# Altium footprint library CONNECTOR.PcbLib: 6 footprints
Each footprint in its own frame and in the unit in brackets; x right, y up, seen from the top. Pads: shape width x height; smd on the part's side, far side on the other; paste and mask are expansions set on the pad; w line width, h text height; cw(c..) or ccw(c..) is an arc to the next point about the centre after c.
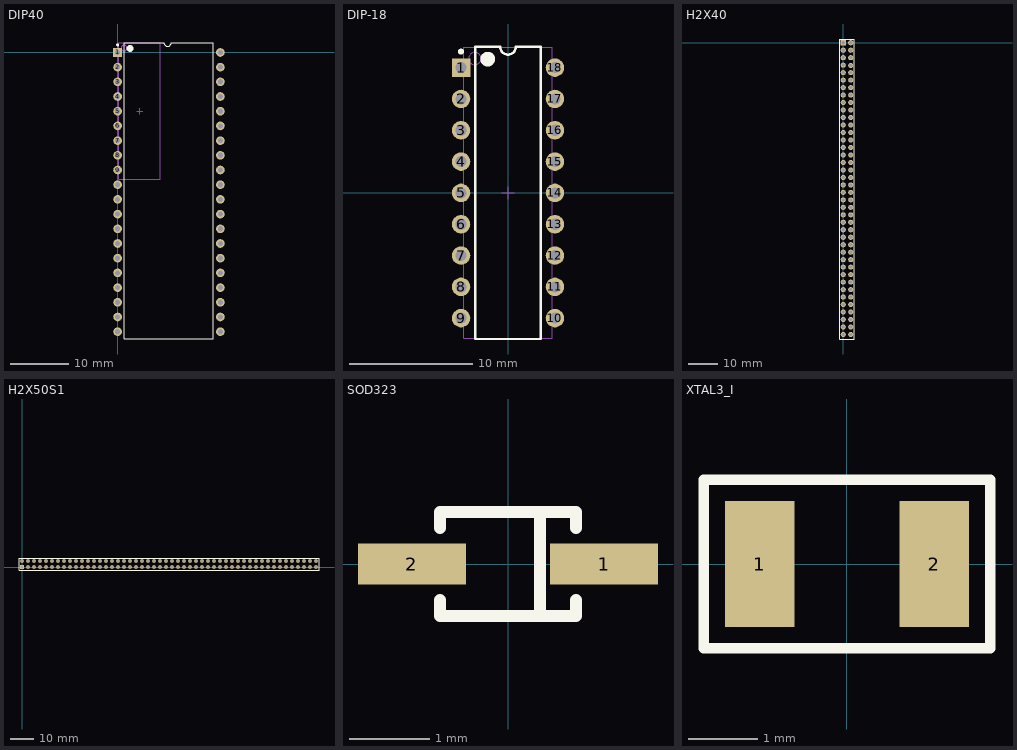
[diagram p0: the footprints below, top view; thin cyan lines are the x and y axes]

## DIP40 [mm] "DIP; 40"
pads (40):
  rect 1.5x1.5 hole 0.9: 1(0,0)
  round 1.5 hole 0.9: 2(0,-2.54) 3(0,-5.08) 4(0,-7.62) 5(0,-10.16) 6(0,-12.7) 7(0,-15.24) 8(0,-17.78) 9(0,-20.32) 10(0,-22.86) 11(0,-25.4) 12(0,-27.94) 13(0,-30.48) 14(0,-33.02) 15(0,-35.56) 16(0,-38.1) 17(0,-40.64) 18(0,-43.18) 19(0,-45.72) 20(0,-48.26) 21(17.78,0) 22(17.78,-2.54) 23(17.78,-5.08) 24(17.78,-7.62) 25(17.78,-10.16) 26(17.78,-12.7) 27(17.78,-15.24) 28(17.78,-17.78) 29(17.78,-20.32) 30(17.78,-22.86) 31(17.78,-25.4) 32(17.78,-27.94) 33(17.78,-30.48) 34(17.78,-33.02) 35(17.78,-35.56) 36(17.78,-38.1) 37(17.78,-40.64) 38(17.78,-43.18) 39(17.78,-45.72) 40(17.78,-48.26)
Top Overlay:
  circle w0.25: c0,1.3 r0.125
  circle w0.6: c2.16,0.69 r0.3
  lines w0.2: 3.175,1.69 1.16,1.69 1.16,-49.53 16.51,-49.53 16.51,1.69
  lines w0.203: 2.54,1.69 8.001,1.69 ccw(c8.636,1.69) 9.271,1.69 16.51,1.69
Mechanical 13:
  circle w0.1: c1.11,0.74 r0.5
  lines w0.1: 0.21,-21.96 0.21,1.64 7.41,1.64 7.41,-21.96 0.21,-21.96
Mechanical 15:
  lines w0.1: 3.31,-10.16 4.31,-10.16 ; 3.81,-10.66 3.81,-9.66

## DIP-18 [mm] "DIP; 18 Leads; Row Spacing 7.62 mm; Pitch 2.54 mm"
height 5.08
pads (18):
  rect 1.5x1.5 hole 0.9: 1(-3.81,10.16)
  round 1.5 hole 0.9: 2(-3.81,7.62) 3(-3.81,5.08) 4(-3.81,2.54) 5(-3.81,0) 6(-3.81,-2.54) 7(-3.81,-5.08) 8(-3.81,-7.62) 9(-3.81,-10.16) 10(3.81,-10.16) 11(3.81,-7.62) 12(3.81,-5.08) 13(3.81,-2.54) 14(3.81,0) 15(3.81,2.54) 16(3.81,5.08) 17(3.81,7.62) 18(3.81,10.16)
Top Overlay:
  circle w0.25: c-3.81,11.46 r0.125
  circle w0.6: c-1.65,10.85 r0.3
  lines w0.2: -2.65,-11.85 -2.65,11.85 -0.635,11.85 ccw(c0,11.85) 0.635,11.85 2.65,11.85 2.65,-11.85 -2.65,-11.85
Mechanical 13:
  circle w0.1: c-2.7,10.9 r0.5
  lines w0.1: -3.6,-11.8 -3.6,11.8 3.6,11.8 3.6,-11.8 -3.6,-11.8
Mechanical 15:
  lines w0.1: -0.5,0 0.5,0 ; 0,-0.5 0,0.5
3D body: height 5.08, standoff 0, extent -3.6,-11.8 3.6,11.8

## H2X40 [mil]
height 330
pads (80):
  rect 68x68 hole 41: 1(0,0)
  round 68 hole 41: 2(100,0) 3(0,-100) 4(100,-100) 5(0,-200) 6(100,-200) 7(0,-300) 8(100,-303) 9(0,-400) 10(100,-400) 11(0,-500) 12(100,-500) 13(0,-600) 14(100,-600) 15(0,-700) 16(100,-700) 17(0,-800) 18(100,-800) 19(0,-900) 20(100,-900) 21(0,-1000) 22(100,-1000) 23(0,-1100) 24(100,-1100) 25(0,-1200) 26(100,-1200) 27(0,-1300) 28(100,-1300) 29(0,-1400) 30(100,-1400) 31(0,-1500) 32(100,-1500) 33(0,-1600) 34(100,-1600) 35(0,-1700) 36(100,-1700) 37(0,-1800) 38(100,-1800) 39(0,-1900) 40(100,-1900) 41(0,-2000) 42(100,-2000) 43(0,-2100) 44(100,-2100) 45(0,-2200) 46(100,-2200) 47(0,-2300) 48(100,-2300) 49(0,-2400) 50(100,-2400) 51(0,-2500) 52(100,-2500) 53(0,-2600) 54(100,-2600) 55(0,-2700) 56(100,-2700) 57(0,-2800) 58(100,-2800) 59(0,-2900) 60(100,-2900) 61(0,-3000) 62(100,-3000) 63(0,-3100) 64(100,-3100) 65(0,-3200) 66(100,-3200) 67(0,-3300) 68(100,-3300) 69(0,-3400) 70(100,-3400) 71(0,-3500) 72(100,-3500) 73(0,-3600) 74(100,-3600) 75(0,-3700) 76(100,-3700) 77(0,-3800) 78(100,-3800) 79(0,-3900) 80(100,-3900)
Top Overlay:
  lines w8: -50,-3960 -50,50 150,50 150,-3960 -50,-3960

## H2X50S1 [mil]
height 330
pads (100):
  rect 62x62 hole 36: 1(0,0)
  round 62 hole 36: 2(0,100) 3(100,0) 4(100,100) 5(200,0) 6(200,100) 7(300,0) 8(300,100) 9(400,0) 10(400,100) 11(500,0) 12(500,100) 13(600,0) 14(600,100) 15(700,0) 16(700,100) 17(800,0) 18(800,100) 19(900,0) 20(900,100) 21(1000,0) 22(1000,100) 23(1100,0) 24(1100,100) 25(1200,0) 26(1200,100) 27(1300,0) 28(1300,100) 29(1400,0) 30(1400,100) 31(1500,0) 32(1500,100) 33(1600,0) 34(1600,100) 35(1700,0) 36(1700,100) 37(1800,0) 38(1800,100) 39(1900,0) 40(1900,100) 41(2000,0) 42(2000,100) 43(2100,0) 44(2100,100) 45(2200,0) 46(2200,100) 47(2300,0) 48(2300,100) 49(2400,0) 50(2400,100) 51(2500,0) 52(2500,100) 53(2600,0) 54(2600,100) 55(2700,0) 56(2700,100) 57(2800,0) 58(2800,100) 59(2900,0) 60(2900,100) 61(3000,0) 62(3000,100) 63(3100,0) 64(3100,100) 65(3200,0) 66(3200,100) 67(3300,0) 68(3300,100) 69(3400,0) 70(3400,100) 71(3500,0) 72(3500,100) 73(3600,0) 74(3600,100) 75(3700,0) 76(3700,100) 77(3800,0) 78(3800,100) 79(3900,0) 80(3900,100) 81(4000,0) 82(4000,100) 83(4100,0) 84(4100,100) 85(4200,0) 86(4200,100) 87(4300,0) 88(4300,100) 89(4400,0) 90(4400,100) 91(4500,0) 92(4500,100) 93(4600,0) 94(4600,100) 95(4700,0) 96(4700,100) 97(4800,0) 98(4800,100) 99(4900,0) 100(4900,100)
Top Overlay:
  lines w10: -50,-50 4950,-50 4950,150 -50,150 -50,-50

## SOD323 [mm]
height 1.118
pads (2):
  rect 1.35x0.508 smd: 1(1.2,0) 2(-1.2,0)
Top Overlay:
  lines w0.152: -0.85,-0.45 -0.85,-0.65 0.85,-0.65 0.85,-0.45 ; -0.85,0.45 -0.85,0.65 0.85,0.65 0.85,0.45 ; 0.4,-0.65 0.4,0.65
3D body: height 1.1, standoff 0, extent -1.325,-0.66 1.275,0.69

## XTAL3_I [mm] "XTAL_CC7V-T1A"
pads (2):
  rect 1x1.8 smd: 1(-1.25,0) 2(1.25,0)
Top Overlay:
  lines w0.152: -2.055,-1.205 -2.055,1.205 2.055,1.205 2.055,-1.205 -2.055,-1.205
